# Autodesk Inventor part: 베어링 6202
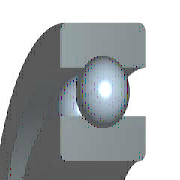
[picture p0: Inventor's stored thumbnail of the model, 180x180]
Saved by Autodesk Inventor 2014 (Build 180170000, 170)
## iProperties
Created: 2015-12
Part Number: 베어링 6202
Material: 강철, 연강
Description: 깊은 그루브 볼 베어링
Document SubType Name: Modeling
Standard: KS B 2023
Designer: mdu
Standards Organization: KS
Language: ko-KR
Size Designation: 6202 - 15 x 35 x 11
Categories: <MemberInstance><Categories><Category DisplayName="샤프트 부품" InternalName="7f7aeb1f-a693-4053-b835-cee3144e0d98" Mnemonic="SHFT"><Category DisplayName="베어링" Inter
Density: 7.86 g/cm^3
Mass: 45.8725 g
Surface Area: 51.5584 cm^2
Volume: 5.83619 cm^3
Appearance: 분홍색
Company: 한국ATC센터
IsCustomPart: 1
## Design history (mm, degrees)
sketch "스케치" dims "d0" = 5.2 (= -0.26 x WD + 0.26 x BD)
  geometry: L1 (2.9, 12.5)-(8.1, 12.5); L2 (5.5, 12.5)-(5.5, 9.9); L3 (5.5, 12.5)-(5.5, 15.1); L4 (3.568, 10.76)-(0, 10.76); L5 (0, 7.5)-(11, 7.5); L6 (3.568, 14.24)-(0, 14.24); L7 (0, 17.5)-(11, 17.5); L8 (11, 7.5)-(11, 10.76); L9 (7.432, 10.76)-(11, 10.76); L10 (7.432, 14.24)-(11, 14.24); L11 (11, 17.5)-(11, 14.24); L12 (-1.4, 0)-(8.4, 0) reference; L13 (0, -0.3)-(0, 5.3) reference
  constraints: 22 end point, 4 point on line, 2 collinear, 2 perpendicular, 2 symmetric about line, 1 midpoint, 1 parallel, 14 other
  dimensions: "d9" = 15 diameter of L5 L12 (= WD); "d11" = 35 diameter of L7 L12 (= BD); "d12" = 11 distance between parallel lines of L8 L13 (= KB); "d13" = 21.52 diameter of L9 L12 (= 0.326 x BD + 0.674 x WD)
revolve "본체" stored, may be unused: angle "d6" = 90 deg
revolve "볼" stored, may be unused: angle "d7" = 90 deg
pattern_circular "IDS_ARRAYBALL[SIMPL:T]" dims angle "d3" = 360 deg
body "Solid1"
fillet "모깎기1" dims "d1" = 0.6 (= KRS)
other parameters: "WD" = 15 [user parameter; used in 5 equation terms], "BD" = 35 [user parameter; used in 5 equation terms], "KB" = 11 [user parameter; used in 1 equation term], "KRS" = 0.6 [user parameter; used in 1 equation term], "d4" = 0, "d5" = 0, "d8" = 0, "d14" = 0, "d15" = 0, "BBA" = 0 [user parameter], "BC0" = 3750000 [user parameter], "BC" = 7800000 [user parameter], "BR" = 17.5 (= 0.5 x BD) [user parameter], "WR" = 7.5 (= 0.5 x WD) [user parameter]
